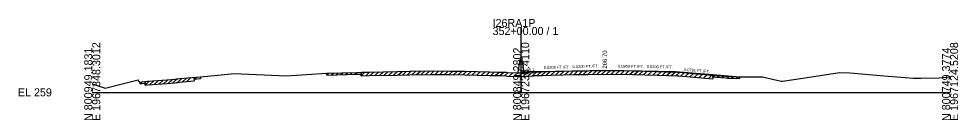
# Model space of a CAD drawing. Extents: x -26 to 304, y -10 to 7527.
# Drawn here: x -25.7 to 302.8, y 990.3 to 1025.6 of the extents above; entities that cross this region are included whole.
import ezdxf

# ---------------------------------------------------------------- set-up
doc = ezdxf.new("R2010")
doc.units = 0
for name, color, linetype in [('RD_GPK_XS_Cell', 7, 'Continuous'), ('RD_XS_Base', 7, 'Continuous'), ('RD_XS_EarthShd', 7, 'Continuous'), ('RD_XS_ExGround', 7, 'Continuous'), ('RD_XS_ExPaveRet', 7, 'Continuous'), ('RD_XS_Misc_Line', 7, 'Continuous'), ('RD_XS_Pave', 7, 'Continuous'), ('RD_XS_PaveShd', 7, 'Continuous'), ('RD_XS_TX_Elev_EX', 7, 'Continuous'), ('RD_XS_TX_Elev_PR', 7, 'Continuous'), ('RD_XS_TX_MkPT', 7, 'Continuous'), ('RD_XS_TX_Profile', 7, 'Continuous'), ('RD_XS_TX_Station', 7, 'Continuous')]:
    doc.layers.add(name, color=color, linetype=linetype)

msp = doc.modelspace()

# ---------------------------------------------------------------- linework, layer by layer
at = {"layer": 'RD_GPK_XS_Cell'}
for p, q in [((150, 1000), (150, 1022.78)), ((0, 1000), (150, 1000)), ((150, 1000), (300, 1000))]:
    msp.add_line(p, q, dxfattribs=at)
at = {"layer": 'RD_XS_Base'}
msp.add_line((150, 1006.82), (150, 1006.98), dxfattribs=at)
at = {"layer": 'RD_XS_EarthShd'}
for p, q in [((149, 1007), (149.67, 1011.48)), ((150, 1011.48), (149.67, 1011.48)), ((150, 1011.48), (150.33, 1011.48)), ((151, 1007), (150.33, 1011.48))]:
    msp.add_line(p, q, dxfattribs=at)
at = {"layer": 'RD_XS_ExGround'}
msp.add_lwpolyline([(0, 1002.94), (4.57, 1001.5), (11.4, 1003.18), (16.11, 1004.36), (16.22, 1003.91), (16.76, 1003.59), (17.44, 1003.72), (19.28, 1003.85), (26.14, 1004.33), (28.92, 1004.62), (29.5, 1004.68), (29.91, 1004.71), (30.54, 1004.77), (37.85, 1005.45), (43.94, 1006.03), (49.72, 1006.54), (52.04, 1006.46), (60.13, 1006.09), (67.89, 1005.78), (74.93, 1006.19), (82.05, 1006.65), (92.48, 1006.95), (94.14, 1007.01), (96.89, 1007.07), (106.59, 1007.29), (110.92, 1007.37), (118.57, 1007.52), (125.2, 1007.43), (130.26, 1007.36), (138.89, 1007.16), (141.93, 1007.08), (142.59, 1007.07), (144.71, 1007), (145.01, 1006.91), (148.47, 1006.81), (149.58, 1006.82), (150, 1006.82), (151.19, 1006.83), (153.89, 1006.95), (154.38, 1006.96), (154.6, 1007.08), (156.06, 1007.13), (157.36, 1007.17), (160.45, 1007.25), (168.97, 1007.47), (173.38, 1007.52), (181.13, 1007.59), (188.92, 1007.45), (193.25, 1007.37), (197.51, 1007.23), (204.67, 1007.01), (205.1, 1006.99), (218.07, 1005.91), (221.4, 1005.66), (222.42, 1005.58), (226.32, 1005.39), (232.33, 1005.44), (233.25, 1005.45), (234.43, 1005.46), (234.92, 1005.34), (240.95, 1003.94), (241.39, 1003.95), (248.54, 1004.99), (261.35, 1006.91), (264.89, 1006.76), (269.02, 1006.48), (275.59, 1005.92), (287.17, 1004.93), (289.82, 1004.92), (296.02, 1005.01), (300, 1005.46)], dxfattribs=at)
at = {"layer": 'RD_XS_ExPaveRet'}
for p, q in [((37.85, 1005.45), (37.85, 1004.82)), ((82.05, 1006.02), (82.05, 1006.65)), ((82.05, 1006.02), (92.48, 1006.33)), ((92.48, 1006.33), (94, 1006.38)), ((94, 1005.76), (94, 1007.01)), ((94, 1007.01), (94, 1006.38)), ((94, 1005.76), (94.14, 1005.76)), ((94.14, 1005.76), (96.89, 1005.82)), ((96.89, 1005.82), (106.59, 1006.04)), ((106.59, 1006.04), (110.92, 1006.12)), ((110.92, 1006.12), (118.57, 1006.27)), ((118.57, 1006.27), (125.2, 1006.18)), ((125.2, 1006.18), (130.26, 1006.11)), ((130.26, 1006.11), (138.89, 1005.91)), ((138.89, 1005.91), (141.93, 1005.83)), ((141.93, 1005.83), (142.59, 1005.82)), ((142.59, 1005.82), (144.71, 1005.75)), ((144.71, 1005.75), (145.01, 1005.66)), ((145.01, 1005.66), (148.47, 1005.56)), ((148.47, 1005.56), (149.58, 1005.57)), ((149.58, 1005.57), (150, 1005.57)), ((150, 1005.57), (151.19, 1005.58)), ((151.19, 1005.58), (153.89, 1005.7)), ((153.89, 1005.7), (154.38, 1005.71)), ((154.38, 1005.71), (154.6, 1005.83)), ((154.6, 1005.83), (156.06, 1005.88)), ((156.06, 1005.88), (157.36, 1005.92)), ((157.36, 1005.92), (160.45, 1006)), ((160.45, 1006), (168.97, 1006.22)), ((168.97, 1006.22), (173.38, 1006.27)), ((173.38, 1006.27), (181.13, 1006.34)), ((181.13, 1006.34), (188.92, 1006.2)), ((188.92, 1006.2), (193.25, 1006.12)), ((193.25, 1006.12), (197.51, 1005.98)), ((197.51, 1005.98), (204.67, 1005.76)), ((204.67, 1005.76), (205.1, 1005.74)), ((205.1, 1005.74), (217.08, 1004.74)), ((217.08, 1005.99), (217.08, 1004.74)), ((217.08, 1005.37), (217.08, 1005.99)), ((217.08, 1005.37), (218.07, 1005.29)), ((226.32, 1005.39), (226.32, 1004.77)), ((16.76, 1002.96), (16.76, 1003.59)), ((16.76, 1002.96), (17.44, 1003.1)), ((17.44, 1003.1), (18.45, 1003.17)), ((18.45, 1002.54), (18.45, 1003.79)), ((18.45, 1003.79), (18.45, 1003.17)), ((18.45, 1002.54), (19.28, 1002.6)), ((19.28, 1002.6), (26.14, 1003.08)), ((26.14, 1003.08), (28.92, 1003.37)), ((28.92, 1003.37), (29.5, 1003.43)), ((29.5, 1003.43), (29.91, 1003.46)), ((29.91, 1003.46), (30.54, 1003.52)), ((30.54, 1003.52), (35.69, 1004)), ((35.69, 1005.25), (35.69, 1004)), ((35.69, 1004.62), (35.69, 1005.25)), ((35.69, 1004.62), (37.85, 1004.82)), ((218.07, 1005.29), (221.4, 1005.04)), ((221.4, 1005.04), (222.42, 1004.96)), ((222.42, 1004.96), (226.32, 1004.77))]:
    msp.add_line(p, q, dxfattribs=at)
at = {"layer": 'RD_XS_Misc_Line'}
for p, q in [((35.69, 1004.62), (36.45, 1005.32)), ((82.05, 1006.02), (82.75, 1006.67)), ((83.67, 1006.07), (84.37, 1006.72)), ((85.29, 1006.12), (85.99, 1006.76)), ((86.92, 1006.17), (87.61, 1006.81)), ((88.54, 1006.21), (89.24, 1006.86)), ((90.16, 1006.26), (90.86, 1006.91)), ((91.78, 1006.31), (92.48, 1006.95)), ((94, 1005.76), (95.38, 1007.04)), ((95.62, 1005.8), (97, 1007.08)), ((97.24, 1005.83), (98.62, 1007.11)), ((98.86, 1005.87), (100.24, 1007.15)), ((100.48, 1005.9), (101.86, 1007.19)), ((102.1, 1005.94), (103.48, 1007.22)), ((103.72, 1005.98), (105.1, 1007.26)), ((105.34, 1006.01), (106.72, 1007.29)), ((106.96, 1006.05), (108.33, 1007.32)), ((108.58, 1006.08), (109.95, 1007.35)), ((110.19, 1006.1), (111.57, 1007.38)), ((111.81, 1006.13), (113.19, 1007.41)), ((113.43, 1006.17), (114.81, 1007.44)), ((115.05, 1006.2), (116.43, 1007.48)), ((116.67, 1006.23), (118.05, 1007.51)), ((118.29, 1006.27), (119.63, 1007.51)), ((119.91, 1006.25), (121.24, 1007.48)), ((121.53, 1006.23), (122.86, 1007.46)), ((123.15, 1006.21), (124.48, 1007.44)), ((124.77, 1006.18), (126.1, 1007.41)), ((126.39, 1006.16), (127.72, 1007.39)), ((128.01, 1006.14), (129.34, 1007.37)), ((129.63, 1006.12), (130.95, 1007.34)), ((131.25, 1006.09), (132.56, 1007.31)), ((132.87, 1006.05), (134.18, 1007.27)), ((134.49, 1006.01), (135.8, 1007.23)), ((136.11, 1005.97), (137.42, 1007.19)), ((137.73, 1005.93), (139.04, 1007.15)), ((139.35, 1005.9), (140.66, 1007.11)), ((140.96, 1005.86), (142.28, 1007.07)), ((142.58, 1005.82), (143.89, 1007.03)), ((144.2, 1005.77), (145.42, 1006.9)), ((145.82, 1005.64), (147.13, 1006.85)), ((147.44, 1005.59), (148.76, 1006.81)), ((149.06, 1005.57), (150.42, 1006.83)), ((150.68, 1005.58), (152.08, 1006.87)), ((152.3, 1005.63), (153.72, 1006.94)), ((153.92, 1005.7), (155.44, 1007.11)), ((155.54, 1005.86), (156.94, 1007.16)), ((157.16, 1005.92), (158.55, 1007.2)), ((158.78, 1005.96), (160.17, 1007.24)), ((160.4, 1006), (161.79, 1007.28)), ((162.02, 1006.04), (163.41, 1007.33)), ((163.64, 1006.08), (165.02, 1007.37)), ((165.26, 1006.12), (166.64, 1007.41)), ((166.88, 1006.16), (168.26, 1007.45)), ((168.5, 1006.2), (169.87, 1007.48)), ((170.12, 1006.23), (171.48, 1007.49)), ((171.73, 1006.25), (173.1, 1007.51)), ((173.35, 1006.27), (174.72, 1007.53)), ((174.97, 1006.28), (176.34, 1007.55)), ((176.59, 1006.3), (177.96, 1007.56)), ((178.21, 1006.31), (179.58, 1007.58)), ((179.83, 1006.33), (181.19, 1007.59)), ((181.45, 1006.34), (182.77, 1007.56)), ((183.07, 1006.31), (184.39, 1007.53)), ((184.69, 1006.28), (186.01, 1007.5)), ((186.31, 1006.25), (187.63, 1007.47)), ((187.93, 1006.22), (189.25, 1007.44)), ((189.55, 1006.19), (190.87, 1007.41)), ((191.17, 1006.16), (192.49, 1007.38)), ((192.79, 1006.13), (194.1, 1007.34)), ((194.41, 1006.08), (195.71, 1007.29)), ((196.03, 1006.03), (197.33, 1007.24)), ((197.65, 1005.98), (198.95, 1007.19)), ((199.27, 1005.93), (200.57, 1007.14)), ((200.88, 1005.88), (202.19, 1007.09)), ((202.5, 1005.83), (203.81, 1007.03)), ((204.12, 1005.78), (205.41, 1006.96)), ((205.74, 1005.68), (206.98, 1006.83)), ((207.36, 1005.55), (208.6, 1006.7)), ((208.98, 1005.42), (210.22, 1006.56)), ((210.6, 1005.28), (211.84, 1006.43)), ((212.22, 1005.15), (213.46, 1006.29)), ((213.84, 1005.01), (215.08, 1006.16)), ((215.46, 1004.88), (216.7, 1006.03)), ((217.08, 1005.37), (217.7, 1005.94)), ((218.7, 1005.24), (219.33, 1005.82)), ((220.33, 1005.12), (220.95, 1005.7)), ((221.95, 1005), (222.58, 1005.58)), ((223.57, 1004.9), (224.21, 1005.5)), ((225.19, 1004.82), (225.83, 1005.42)), ((16.76, 1002.96), (17.59, 1003.73)), ((18.45, 1002.54), (19.91, 1003.9)), ((20.07, 1002.66), (21.53, 1004.01)), ((21.69, 1002.77), (23.15, 1004.12)), ((23.31, 1002.88), (24.77, 1004.24)), ((24.93, 1003), (26.4, 1004.36)), ((26.55, 1003.12), (28.07, 1004.53)), ((28.17, 1003.29), (29.69, 1004.69)), ((29.79, 1003.45), (31.29, 1004.84)), ((31.41, 1003.6), (32.91, 1004.99)), ((33.03, 1003.75), (34.53, 1005.14))]:
    msp.add_line(p, q, dxfattribs=at)
at = {"layer": 'RD_XS_Pave'}
for p, q in [((156, 1007.22), (180, 1007.7)), ((180, 1007.7), (204, 1007.22)), ((204, 1007.22), (217.08, 1006.18))]:
    msp.add_line(p, q, dxfattribs=at)
at = {"layer": 'RD_XS_PaveShd'}
for p, q in [((156, 1007.22), (150, 1006.98)), ((217.08, 1006.18), (226.32, 1005.39))]:
    msp.add_line(p, q, dxfattribs=at)
at = {"layer": 'RD_XS_TX_Elev_PR'}
for p, q in [((150, 1006.82), (151.19, 1006.83)), ((151.19, 1006.83), (153.89, 1006.95)), ((153.89, 1006.95), (154.38, 1006.96)), ((154.38, 1006.96), (154.6, 1007.08)), ((154.6, 1007.08), (156.06, 1007.13)), ((156.06, 1007.13), (157.36, 1007.17)), ((157.36, 1007.17), (160.45, 1007.25)), ((160.45, 1007.25), (168.97, 1007.47)), ((168.97, 1007.47), (173.38, 1007.52)), ((173.38, 1007.52), (181.13, 1007.59)), ((181.13, 1007.59), (188.92, 1007.45)), ((188.92, 1007.45), (193.25, 1007.37)), ((193.25, 1007.37), (197.51, 1007.23)), ((197.51, 1007.23), (204, 1007.03)), ((204.67, 1007.01), (204, 1007.03)), ((204.67, 1007.01), (205.1, 1006.99)), ((205.1, 1006.99), (211.58, 1006.45)), ((211.58, 1006.45), (218.07, 1005.91)), ((218.07, 1005.91), (221.4, 1005.66)), ((221.4, 1005.66), (222.42, 1005.58)), ((222.42, 1005.58), (224.37, 1005.49)), ((224.37, 1005.49), (226.32, 1005.39))]:
    msp.add_line(p, q, dxfattribs=at)

# ---------------------------------------------------------------- texts
at = {"layer": 'RD_GPK_XS_Cell'}
for s, p in [('I26RA1P', (140, 1022.78)), ('352+00.00 / 1', (140, 1019.98)), ('EL 259', (-26, 998.6))]:
    msp.add_text(s, height=2.8, dxfattribs=at).set_placement(p)
for s, p in [('N 800949.1831', (0, 990)), ('E 1967348.3012', (2.8, 990)), ('N 800849.2802', (150, 990)), ('E 1967236.4110', (152.8, 990)), ('N 800749.3774', (300, 990)), ('E 1967124.5208', (302.8, 990))]:
    msp.add_text(s, height=2.8, rotation=90, dxfattribs=at).set_placement(p)
at = {"layer": 'RD_XS_TX_Elev_EX'}
msp.add_text('265.82', height=1, rotation=90, dxfattribs=at).set_placement((151, 1006.82))
at = {"layer": 'RD_XS_TX_MkPT'}
msp.add_text('25:1', height=1, rotation=2.2906, dxfattribs=at).set_placement((151.94, 1007.3))
at = {"layer": 'RD_XS_TX_Profile'}
for s, rotation, p in [('0.0200 FT./FT.', 1.1458, (157.92, 1008.14)), ('0.0200 FT./FT.', 1.1458, (167.98, 1008.46)), ('0.0200 FT./FT.', 358.8542, (183.83, 1008.62)), ('0.0200 FT./FT.', 358.8542, (193.89, 1008.5)), ('0.0791 FT./FT.', 355.4753, (206.88, 1007.46))]:
    msp.add_text(s, height=1, rotation=rotation, dxfattribs=at).set_placement(p)
at = {"layer": 'RD_XS_TX_Station'}
msp.add_text(' 266.70', height=1.5, rotation=90, dxfattribs=at).set_placement((180, 1007.7))

doc.saveas('drawing.dxf')
